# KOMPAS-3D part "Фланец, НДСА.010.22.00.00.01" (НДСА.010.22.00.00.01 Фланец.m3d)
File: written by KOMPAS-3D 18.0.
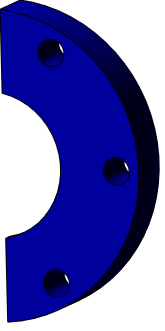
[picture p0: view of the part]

Document properties: Полное имя файла: F:\Temp\НДСА.010.22.00.00.01 Фланец.m3d

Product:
- Part/product: Фланец  | designation НДСА.010.22.00.00.01
    Материал: Д16 ГОСТ 4784-97 (density 2800 kg/m3)
    Масса: 0.0195752
    additional columns: <item xmlns="http://appius.ru/pdm" xmlns:xs="http://www.w3.org/2001/XMLSchema" x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; <item xmlns="http://appius.ru/pdm" xmlns:xs="http://www.w3.org/2001/XMLSchema" x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; <item xmlns="http://appius.ru/pdm" xmlns:xs="http://www.w3.org/2001/XMLSchema" x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; <item xmlns="http://appius.ru/pdm" xmlns:xs="http://www.w3.org/2001/XMLSchema" x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; <item xmlns="http://appius.ru/pdm" xmlns:xs="http://www.w3.org/2001/XMLSchema" x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; <item xmlns="http://appius.ru/pdm" xmlns:xs="http://www.w3.org/2001/XMLSchema" x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; <item xmlns="http://appius.ru/pdm" xmlns:xs="http://www.w3.org/2001/XMLSchema" x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; <item xmlns="http://appius.ru/pdm" xmlns:xs="http://www.w3.org/2001/XMLSchema" x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

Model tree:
1. Операция без истории:1
2. Эскиз:1  (with: Операция без истории:1)
3. Элемент выдавливания:1
     Расстояние 2 = 9.85
4. Эскиз:2  (with: Операция без истории:1)
5. Элемент выдавливания:2
     Расстояние 2 = 9.85
6. Эскиз:3  (with: Операция без истории:1)
7. Элемент выдавливания:3
     Расстояние 2 = 9.85
8. Массив по концентрической сетке:1  (with: Элемент выдавливания:3)  (labels: Д16 ГОСТ 4784-97; SYSTEM_PROPERTY_ADDITIONAL_FOR:9.000000)  (6 pattern instances)
     Шаг 2 = 360

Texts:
  НДСА.010.22.00.00.01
